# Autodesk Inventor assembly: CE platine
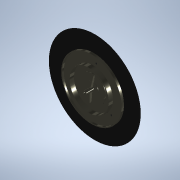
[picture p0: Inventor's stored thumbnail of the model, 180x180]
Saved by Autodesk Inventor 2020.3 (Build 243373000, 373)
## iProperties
Created: 2020-09
Part Number: CE platine
Document SubType Name: Assembly
Designer: ficho
Mass: 469.106 g
Surface Area: 2298.55 cm^2
Volume: 375.91 cm^3
Density: 1.24792 g/cm^3
Author: ficho
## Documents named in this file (4)
- G:\travail\année 2020-2021\2I2D\platine disque\platine 3D\CE platine.iam
- G:\travail\année 2020-2021\2I2D\platine disque\platine 3D\platine.ipt
- G:\travail\année 2020-2021\2I2D\platine disque\platine 3D\touche porte disque.ipt
- G:\travail\année 2020-2021\2I2D\platine disque\platine 3D\vinyle floqué.ipt
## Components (5 placed, 3 different names)
1. platine:1 — Logement:1, Logement:2, Logement:3, Placage:1
2. touche porte disque:1 — Logement:1
3. touche porte disque:2 — Logement:2, Placage:2
4. touche porte disque:3 — Logement:3
5. vinyle floqué:1 — Placage:1, Placage:2
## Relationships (5: Insert 3, Mate 2)
- Logement:1 [Insert]: platine:1 ↔ touche porte disque:1
- Logement:2 [Insert]: platine:1 ↔ touche porte disque:2
- Logement:3 [Insert]: platine:1 ↔ touche porte disque:3
- Placage:1 [Mate]: platine:1 ↔ vinyle floqué:1
- Placage:2 [Mate]: touche porte disque:2 ↔ vinyle floqué:1
